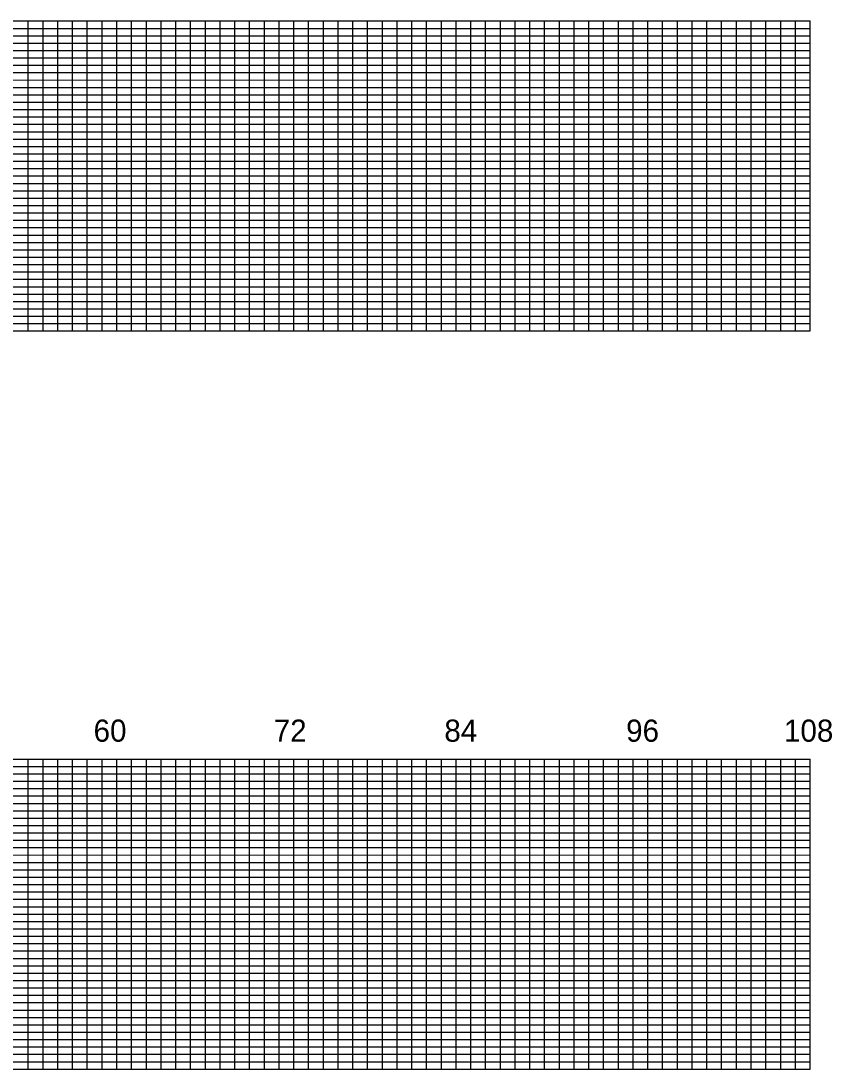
# Model space of a CAD drawing. Extents: x 1914168 to 1925341, y 720939 to 777401.
# Drawn here: x 1917069 to 1919818, y 720964 to 724514 of the extents above; entities that cross this region are included whole.
import ezdxf

# ---------------------------------------------------------------- set-up
doc = ezdxf.new("R2010")
doc.units = 0
doc.layers.add('RD_PD_WallFill', color=7, linetype='Continuous')

msp = doc.modelspace()

# ---------------------------------------------------------------- linework, layer by layer
at = {"layer": 'RD_PD_WallFill'}
for p, q in [((1914394, 724514.1), (1919744, 724514.2)), ((1914844, 724489.1), (1919744, 724489.1)), ((1917094, 723464.2), (1917094, 724514.2)), ((1917144, 723464.2), (1917144, 724514.2)), ((1917194, 723464.2), (1917194, 724514.2)), ((1917244, 723464.2), (1917244, 724514.2)), ((1917294, 723464.2), (1917294, 724514.2)), ((1917344, 723464.2), (1917344, 724514.2)), ((1917394, 723464.2), (1917394, 724514.2)), ((1917444, 723464.2), (1917444, 724514.2)), ((1917494, 723464.1), (1917494, 724514.2)), ((1917544, 723464.2), (1917544, 724514.2)), ((1917594, 723464.2), (1917594, 724514.2)), ((1917644, 723464.2), (1917644, 724514.2)), ((1917694, 723464.2), (1917694, 724514.2)), ((1917744, 723464.2), (1917744, 724514.2)), ((1917794, 723464.1), (1917794, 724514.2)), ((1917844, 723464.1), (1917844, 724514.2)), ((1917894, 723464.2), (1917894, 724514.2)), ((1917944, 723464.2), (1917944, 724514.2)), ((1917994, 723464.2), (1917994, 724514.2)), ((1918044, 723464.2), (1918044, 724514.2)), ((1918094, 723464.2), (1918094, 724514.2)), ((1918144, 723464.2), (1918144, 724514.2)), ((1918194, 723464.2), (1918194, 724514.2)), ((1918244, 723464.2), (1918244, 724514.2)), ((1918294, 723464.2), (1918294, 724514.2)), ((1918344, 723464.2), (1918344, 724514.2)), ((1918394, 723464.2), (1918394, 724514.2)), ((1918444, 723464.2), (1918444, 724514.2)), ((1918494, 723464.2), (1918494, 724514.2)), ((1918544, 723464.2), (1918544, 724514.2)), ((1918594, 723464.2), (1918594, 724514.2)), ((1918644, 723464.2), (1918644, 724514.2)), ((1918694, 723464.2), (1918694, 724514.2)), ((1918744, 723464.2), (1918744, 724514.2)), ((1918794, 723464.2), (1918794, 724514.2)), ((1918844, 723464.2), (1918844, 724514.2)), ((1918894, 723464.2), (1918894, 724514.2)), ((1918944, 723464.2), (1918944, 724514.2)), ((1918994, 723464.2), (1918994, 724514.2)), ((1919044, 723464.2), (1919044, 724514.2)), ((1919094, 723464.2), (1919094, 724514.2)), ((1919144, 723464.2), (1919144, 724514.2)), ((1919194, 723464.2), (1919194, 724514.2)), ((1919244, 723464.2), (1919244, 724514.2)), ((1919294, 723464.2), (1919294, 724514.2)), ((1919344, 723464.2), (1919344, 724514.2)), ((1919394, 723464.2), (1919394, 724514.2)), ((1919444, 723464.2), (1919444, 724514.2)), ((1919494, 723464.2), (1919494, 724514.2)), ((1919544, 723464.2), (1919544, 724514.2)), ((1919594, 723464.2), (1919594, 724514.2)), ((1919644, 723464.2), (1919644, 724514.2)), ((1919694, 723464.2), (1919694, 724514.2)), ((1919744, 723464.2), (1919744, 724514.2)), ((1914844, 724464.1), (1919744, 724464.1)), ((1914844, 724439.1), (1919744, 724439.1)), ((1914844, 724414.2), (1919744, 724414.1)), ((1914844, 724389.1), (1919744, 724389.2)), ((1914394, 724364.1), (1919744, 724364.1)), ((1914394, 724339.1), (1919744, 724339.1)), ((1914394, 724314.1), (1919744, 724314.2)), ((1914394, 724289.2), (1919744, 724289.1)), ((1914394, 724264.2), (1919744, 724264.2)), ((1914394, 724239.1), (1919744, 724239.1)), ((1914394, 724214.1), (1919744, 724214.1)), ((1914394, 724189.2), (1919744, 724189.1)), ((1914394, 724164.1), (1919744, 724164.1)), ((1914394, 724139.2), (1919744, 724139.1)), ((1914394, 724114.1), (1919744, 724114.1)), ((1914394, 724089.1), (1919744, 724089.2)), ((1914394, 724064.1), (1919744, 724064.1)), ((1914394, 724039.1), (1919744, 724039.2)), ((1914394, 724014.1), (1919744, 724014.1)), ((1914394, 723989.1), (1919744, 723989.1)), ((1914394, 723964.2), (1919744, 723964.1)), ((1914394, 723939.1), (1919744, 723939.1)), ((1914394, 723914.1), (1919744, 723914.1)), ((1914394, 723889.1), (1919744, 723889.1)), ((1914394, 723864.1), (1919744, 723864.2)), ((1914394, 723839.1), (1919744, 723839.1)), ((1914394, 723814.1), (1919744, 723814.1)), ((1914394, 723789.1), (1919744, 723789.1)), ((1914394, 723764.1), (1919744, 723764.1)), ((1914394, 723739.1), (1919744, 723739.1)), ((1914394, 723714.1), (1919744, 723714.1)), ((1914394, 723689.1), (1919744, 723689.1)), ((1914394, 723664.1), (1919744, 723664.1)), ((1914394, 723639.1), (1919744, 723639.1)), ((1914394, 723614.1), (1919744, 723614.1)), ((1914394, 723589.1), (1919744, 723589.1)), ((1914394, 723564.1), (1919744, 723564.1)), ((1914394, 723539.1), (1919744, 723539.1)), ((1914394, 723514.1), (1919744, 723514.1)), ((1914394, 723464.1), (1919744, 723464.1)), ((1914444, 723489.1), (1919744, 723489.1)), ((1914394, 722014.1), (1919744, 722014.2)), ((1917094, 720964.2), (1917094, 722014.2)), ((1917144, 720964.2), (1917144, 722014.2)), ((1917194, 720964.2), (1917194, 722014.2)), ((1917244, 720964.2), (1917244, 722014.2)), ((1917294, 720964.2), (1917294, 722014.2)), ((1917344, 720964.2), (1917344, 722014.2)), ((1917394, 720964.2), (1917394, 722014.2)), ((1917444, 720964.2), (1917444, 722014.2)), ((1917494, 720964.1), (1917494, 722014.2)), ((1917544, 720964.2), (1917544, 722014.2)), ((1917594, 720964.2), (1917594, 722014.2)), ((1917644, 720964.2), (1917644, 722014.2)), ((1917694, 720964.2), (1917694, 722014.2)), ((1917744, 720964.2), (1917744, 722014.2)), ((1917794, 720964.1), (1917794, 722014.2)), ((1917844, 720964.1), (1917844, 722014.2)), ((1917894, 720964.2), (1917894, 722014.2)), ((1917944, 720964.2), (1917944, 722014.2)), ((1917994, 720964.2), (1917994, 722014.2)), ((1918044, 720964.2), (1918044, 722014.2)), ((1918094, 720964.2), (1918094, 722014.2)), ((1918144, 720964.2), (1918144, 722014.2)), ((1918194, 720964.2), (1918194, 722014.2)), ((1918244, 720964.2), (1918244, 722014.2)), ((1918294, 720964.2), (1918294, 722014.2)), ((1918344, 720964.2), (1918344, 722014.2)), ((1918394, 720964.2), (1918394, 722014.2)), ((1918444, 720964.2), (1918444, 722014.2)), ((1918494, 720964.2), (1918494, 722014.2)), ((1918544, 720964.2), (1918544, 722014.2)), ((1918594, 720964.2), (1918594, 722014.2)), ((1918644, 720964.2), (1918644, 722014.2)), ((1918694, 720964.2), (1918694, 722014.2)), ((1918744, 720964.2), (1918744, 722014.2)), ((1918794, 720964.2), (1918794, 722014.2)), ((1918844, 720964.2), (1918844, 722014.2)), ((1918894, 720964.2), (1918894, 722014.2)), ((1918944, 720964.2), (1918944, 722014.2)), ((1918994, 720964.2), (1918994, 722014.2)), ((1919044, 720964.2), (1919044, 722014.2)), ((1919094, 720964.2), (1919094, 722014.2)), ((1919144, 720964.2), (1919144, 722014.2)), ((1919194, 720964.2), (1919194, 722014.2)), ((1919244, 720964.2), (1919244, 722014.2)), ((1919294, 720964.2), (1919294, 722014.2)), ((1919344, 720964.2), (1919344, 722014.2)), ((1919394, 720964.2), (1919394, 722014.2)), ((1919444, 720964.2), (1919444, 722014.2)), ((1919494, 720964.2), (1919494, 722014.2)), ((1919544, 720964.2), (1919544, 722014.2)), ((1919594, 720964.2), (1919594, 722014.2)), ((1919644, 720964.2), (1919644, 722014.2)), ((1919694, 720964.2), (1919694, 722014.2)), ((1919744, 720964.2), (1919744, 722014.2)), ((1914844, 721989.1), (1919744, 721989.1)), ((1914844, 721964.1), (1919744, 721964.1)), ((1914844, 721939.1), (1919744, 721939.1)), ((1914844, 721914.2), (1919744, 721914.1)), ((1914394, 721864.1), (1919744, 721864.1)), ((1914844, 721889.1), (1919744, 721889.2)), ((1914394, 721839.1), (1919744, 721839.1)), ((1914394, 721814.1), (1919744, 721814.2)), ((1914394, 721789.2), (1919744, 721789.1)), ((1914394, 721764.2), (1919744, 721764.2)), ((1914394, 721739.1), (1919744, 721739.1)), ((1914394, 721714.1), (1919744, 721714.1)), ((1914394, 721689.2), (1919744, 721689.1)), ((1914394, 721664.1), (1919744, 721664.1)), ((1914394, 721639.2), (1919744, 721639.1)), ((1914394, 721614.1), (1919744, 721614.1)), ((1914394, 721589.1), (1919744, 721589.2)), ((1914394, 721564.1), (1919744, 721564.1)), ((1914394, 721539.1), (1919744, 721539.2)), ((1914394, 721514.1), (1919744, 721514.1)), ((1914394, 721489.1), (1919744, 721489.1)), ((1914394, 721464.2), (1919744, 721464.1)), ((1914394, 721439.1), (1919744, 721439.1)), ((1914394, 721414.1), (1919744, 721414.1)), ((1914394, 721389.1), (1919744, 721389.1)), ((1914394, 721364.1), (1919744, 721364.2)), ((1914394, 721339.1), (1919744, 721339.1)), ((1914394, 721314.1), (1919744, 721314.1)), ((1914394, 721289.1), (1919744, 721289.1)), ((1914394, 721264.1), (1919744, 721264.1)), ((1914394, 721239.1), (1919744, 721239.1)), ((1914394, 721214.1), (1919744, 721214.1)), ((1914394, 721189.1), (1919744, 721189.1)), ((1914394, 721164.1), (1919744, 721164.1)), ((1914394, 721139.1), (1919744, 721139.1)), ((1914394, 721114.1), (1919744, 721114.1)), ((1914394, 721089.1), (1919744, 721089.1)), ((1914394, 721064.1), (1919744, 721064.1)), ((1914394, 721039.1), (1919744, 721039.1)), ((1914394, 721014.1), (1919744, 721014.1)), ((1914444, 720989.1), (1919744, 720989.1)), ((1914394, 720964.1), (1919744, 720964.1))]:
    msp.add_line(p, q, dxfattribs=at)

# ---------------------------------------------------------------- texts
for s, p in [('60', (1917315.2, 722072.8)), ('72', (1917925.8, 722072.8)), ('84', (1918504.1, 722072.8)), ('96', (1919120.2, 722072.8)), ('108', (1919655.2, 722072.8))]:
    msp.add_text(s, height=75, dxfattribs=at).set_placement(p)

doc.saveas('drawing.dxf')
